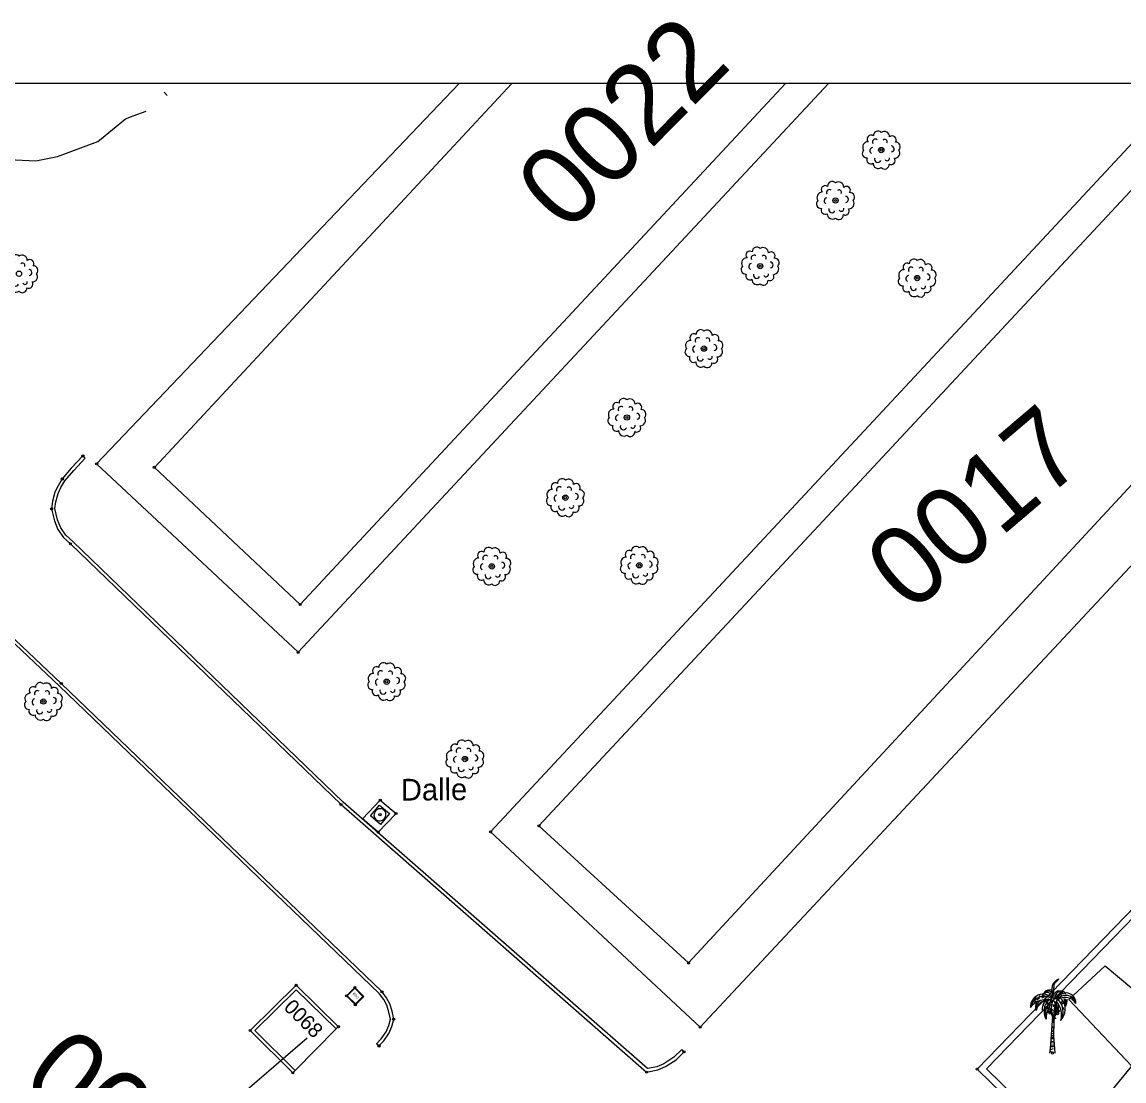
# Model space of a CAD drawing. Extents: x 344013 to 344423, y 298505 to 298795.
# Drawn here: x 344171.7 to 344222.4, y 298745.9 to 298794.7 of the extents above; entities that cross this region are included whole.
import ezdxf

# ---------------------------------------------------------------- set-up
doc = ezdxf.new("R2010")
doc.units = 0
for name, color, linetype in [('Default', 7, 'Continuous'), ('DH_CADRE -CARTOUCHE', 7, 'Continuous'), ('PC_CONCRETE', 7, 'Continuous'), ('PS_BOLT', 7, 'Continuous'), ('PS_CONST', 7, 'Continuous'), ('RES_ELECTRICITE', 7, 'Continuous'), ('TOPO_COURBE NIVEAU', 7, 'Continuous'), ('TOPO_POINT', 7, 'Continuous'), ('TOPO_TALUS-TERRAIN NATUREL', 7, 'Continuous'), ('VOIRIE_BORDURE', 7, 'Continuous'), ('VOIRIE_ESPACE VERT', 7, 'Continuous')]:
    doc.layers.add(name, color=color, linetype=linetype)

# ---------------------------------------------------------------- blocks, each defined once
blk = doc.blocks.new('REG_INC')
at = {"layer": 'Default'}
for p, q in [((0, 1), (1, 1)), ((0, 0), (0, 1)), ((1, 1), (1, 0)), ((1, 0), (0, 0))]:
    blk.add_line(p, q, dxfattribs=at)
for centre, start, end in [((0.498, 0.5), 135.00554, 180.00554), ((0.5, 0.498), 90.00577, 135.00577), ((0.5, 0.5), 45.00687, 90.00687), ((0.499, 0.499), 0.00663, 45.00663), ((0.501, 0.5), 180.00663, 225.00663), ((0.499, 0.498), 225.00686, 270.00686), ((0.499, 0.5), 270.00577, 315.00577), ((0.501, 0.499), 315.00554, 0.00554)]:
    blk.add_arc(centre, 0.44, start, end, dxfattribs=at)
blk = doc.blocks.new('RES_ELECTRICITE')
at = {"layer": 'RES_ELECTRICITE'}
for points in [[(0, 0), (0, 1), (1, 1), (1, 0)], [(0.05, 0.05), (0.05, 0.95), (0.95, 0.95), (0.95, 0.05)]]:
    blk.add_lwpolyline(points, close=True, dxfattribs=at)
blk.add_text('EEC', height=0.2, dxfattribs=at).set_placement((0.237, 0.46))
blk = doc.blocks.new('POINT_DISPLAY')
at = {"layer": 'Default'}
blk.add_circle((0, 0), 0.05, dxfattribs=at)
blk = doc.blocks.new('COCO')
at = {"layer": 'Default'}
for p, q in [((-0.037, 1.06), (0.056, 1.071)), ((0.058, 1.14), (-0.03, 1.162)), ((-0.026, 1.226), (0.061, 1.212)), ((-0.062, 0.537), (0.046, 0.552)), ((0.047, 0.655), (-0.058, 0.642)), ((-0.046, 0.891), (0.052, 0.927)), ((0.054, 0.998), (-0.041, 0.985)), ((0.046, 0.033), (-0.076, 0.051)), ((-0.073, 0.17), (0.045, 0.209)), ((0.045, 0.292), (-0.07, 0.288)), ((-0.068, 0.371), (0.045, 0.374)), ((0.045, 0.47), (-0.065, 0.453))]:
    blk.add_line(p, q, dxfattribs=at)
for points in [[(0.029, 2.551), (-0.016, 2.896), (0.002, 3.125), (0.059, 3.241), (0.173, 3.348), (0.189, 3.356), (0.282, 3.415), (0.266, 3.373), (0.2, 3.318), (0.143, 3.247), (0.093, 3.2), (0.081, 3.165), (0.057, 3.133), (0.057, 3.099), (0.06, 3.037), (0.039, 2.989), (0.039, 2.944), (0.049, 2.877), (0.037, 2.841), (0.013, 2.736)], [(-0.746, 2.559), (-0.864, 2.483)], [(-0.636, 2.639), (-0.541, 2.608)], [(-0.421, 2.58), (-0.503, 2.523)], [(-0.487, 2.68), (-0.386, 2.65)], [(-0.256, 2.553), (-0.385, 2.508)], [(0.013, 2.736), (0.036, 2.813), (0.046, 2.746)], [(0.133, 2.608), (0.185, 2.634)], [(0.196, 2.687), (0.323, 2.715)], [(0.283, 2.765), (0.331, 2.786)], [(-0.77, 2.413), (-0.836, 2.333)], [(-0.607, 2.534), (-0.704, 2.443)], [(-0.183, 2.493), (-0.348, 2.417), (-0.401, 2.307), (-0.448, 2.203), (-0.471, 2.086), (-0.474, 2.023), (-0.466, 1.973), (-0.455, 2.054), (-0.451, 2.146), (-0.387, 2.292), (-0.351, 2.354), (-0.284, 2.404), (-0.233, 2.445), (-0.012, 2.495)], [(-0.276, 2.151), (-0.329, 2.086)], [(-0.203, 2.314), (-0.274, 2.258)], [(-0.23, 2.152), (-0.237, 2.043)], [(-0.161, 2.218), (-0.158, 2.122)], [(-0.04, 2.247), (-0.081, 2.179)], [(0.015, 2.414), (-0.056, 2.352)], [(-0.025, 2.032), (0.002, 1.954)], [(0.022, 2.24), (0.043, 2.13)], [(0.081, 2.404), (0.106, 2.299)], [(0.385, 2.37), (0.469, 2.254)], [(0.473, 2.115), (0.509, 2.012)], [(-0.321, 1.997), (-0.364, 1.9)], [(-0.059, 2.024), (-0.083, 1.998)], [(-0.055, 0.716), (0.048, 0.717), (0.049, 0.787), (-0.051, 0.795)]]:
    blk.add_lwpolyline(points, dxfattribs=at)
for centre, radius in [((-0.144, 1.978), 0.0616), ((-0.187, 1.897), 0.0384), ((-0.124, 1.896), 0.0376), ((-0.11, 1.84), 0.0471), ((0.134, 1.862), 0.0549), ((0.208, 1.822), 0.0626), ((0.254, 1.938), 0.0628)]:
    blk.add_circle(centre, radius, dxfattribs=at)
for centre, radius, start, end in [((-0.427, 2.113), 0.595, 43.6121, 181.4625), ((-0.38, 1.964), 0.648, 57.9192, 166.6201), ((-0.123, 2.59), 0.323, 122.3475, 158.7636), ((-0.199, 2.618), 0.238, 4.5218, 154.101), ((-0.252, 2.556), 0.231, 4.2441, 134.2103), ((-0.16, 2.647), 0.255, 21.0861, 122.3475), ((0.376, 2.508), 0.372, 113.7681, 175.3309), ((0.376, 2.508), 0.372, 113.7681, 175.3309), ((0.418, 2.527), 0.326, 97.1248, 183.9512), ((1.025, 2.053), 0.958, 126.6858, 153.1664), ((0.59, 2.015), 0.548, 29.5654, 139.3517), ((0.618, 2.316), 0.451, 356.1627, 159.0009), ((0.609, 2.187), 0.468, 12.1077, 148.3146), ((0.344, 2.407), 0.451, 69.0817, 104.862), ((-0.157, 2.027), 0.74, 51.2475, 54.5217), ((-1.005, 1.577), 1.786, 37.5668, 40.5156), ((-0.254, 2.28), 0.869, 28.4725, 37.0965), ((0.493, 2.767), 0.0679, 35.3205, 126.6858), ((-0.054, 2.379), 0.738, 25.8194, 35.3205), ((-0.291, 1.543), 0.918, 76.7389, 142.8025), ((-0.3, 2.12), 0.482, 151.1331, 199.5942), ((-0.196, 1.874), 0.565, 78.514, 171.3504), ((-0.32, 2.055), 0.433, 119.0834, 188.7621), ((0.362, 1.922), 0.754, 136.7113, 208.8221), ((0.551, 1.79), 0.879, 137.733, 194.3716), ((0.649, 1.599), 0.949, 145.5146, 182.4528), ((0.62, 2.159), 0.753, 153.0868, 230.1124), ((0.659, 2.068), 0.718, 142.3554, 222.2794), ((-0.007, 2.465), 0.0563, 81.7475, 144.3035), ((-0.189, 1.21), 1.324, 71.3715, 81.7475), ((0.294, 2.595), 0.256, 198.6765, 199.7627), ((0.963, 1.939), 0.9, 143.9866, 203.4288), ((0.544, 1.816), 0.474, 137.1953, 172.8987), ((0.308, 2.014), 0.226, 121.4297, 182.29), ((27.302, 0.106), 27.266, 175.4791, 176.5597), ((0.311, 2.152), 0.219, 141.856, 191.5175), ((0.372, 1.847), 0.277, 133.5956, 173.487), ((0.242, 1.964), 0.147, 110.9727, 165.9756), ((0.404, 1.878), 0.354, 125.0585, 146.3893), ((0.398, 2.098), 0.301, 136.4569, 162.0685), ((0.357, 2.084), 0.244, 133.1184, 172.7534), ((-0.759, 1.958), 0.922, 344.8505, 15.8988), ((-0.404, 2.045), 0.619, 329.4666, 26.6793), ((-0.289, 2.11), 0.564, 317.8279, 12.3386), ((-0.543, 1.744), 0.96, 344.8781, 41.1461), ((-0.341, 1.9), 0.828, 46.9767, 50.1231), ((-0.341, 1.9), 0.828, 334.0687, 41.194), ((-0.157, 2.027), 0.74, 315.1472, 39.0239), ((-1.704, 1.849), 2.327, 7.5978, 16.3666), ((-0.254, 2.28), 0.869, 350.8883, 14.7063), ((-0.482, 2.552), 1.161, 339.3597, 356.5925), ((-85.428, 7.294), 85.622, 355.11326, 356.26352), ((-0.279, 1.637), 0.281, 2.1499, 36.6325), ((-0.265, 1.505), 0.316, 339.9997, 25.7228), ((0.199, 1.66), 0.176, 166.9443, 185.5966), ((0.808, 1.542), 0.777, 142.2358, 156.28)]:
    blk.add_arc(centre, radius, start, end, dxfattribs=at)
blk.add_ellipse((27.425, 0.272), major_axis=(-27.371, 0.966), ratio=0.529859, start_param=6.255729, end_param=6.369141, dxfattribs=at)
blk = doc.blocks.new('ARB1')
at = {"layer": 'Default'}
blk.add_circle((0, 0), 0.122, dxfattribs=at)
for centre, radius, start, end in [((-0.471, 0.503), 0.183, 53.9554, 222.2066), ((-0.153, 0.664), 0.211, 43.6925, 183.5969), ((0.139, 0.613), 0.241, 358.4583, 125.1928), ((0.501, 0.468), 0.183, 325.1444, 131.0175), ((-0.613, 0.139), 0.241, 88.4583, 215.1928), ((-0.373, -0.024), 0.149, 103.7092, 242.3465), ((-0.276, 0.37), 0.134, 52.4396, 209.5496), ((0.164, 0.38), 0.112, 330.5895, 133.7127), ((0.458, 0.052), 0.137, 276.6214, 88.967), ((0.613, -0.139), 0.241, 268.4583, 35.1928), ((0.664, 0.153), 0.211, 313.6925, 93.5969), ((-0.664, -0.153), 0.211, 133.6925, 273.5969), ((-0.478, -0.443), 0.19, 155.2243, 300.9377), ((-0.163, -0.42), 0.148, 159.5371, 338.1663), ((0.271, -0.38), 0.112, 210.5895, 13.7127), ((0.448, -0.483), 0.188, 243.1323, 33.0297), ((-0.139, -0.613), 0.241, 178.4583, 305.1928), ((0.153, -0.664), 0.211, 223.6925, 3.5969)]:
    blk.add_arc(centre, radius, start, end, dxfattribs=at)

msp = doc.modelspace()

# ---------------------------------------------------------------- linework, layer by layer
at = {"layer": 'DH_CADRE -CARTOUCHE'}
for points in [[(344012.906, 298504.876), (344422.906, 298504.876), (344422.906, 298791.876), (344012.906, 298791.876)], [(344194.197, 298791.876), (344177.741, 298774.193), (344184.453, 298767.878), (344206.795, 298791.876)], [(344227.296, 298791.876), (344195.443, 298757.689), (344202.327, 298751.376), (344235.016, 298786.657), (344229.42, 298791.876)], [(344186.218, 298748.441), (344186.113, 298748.334), (344184.269, 298750.136), (344182.367, 298748.262), (344184.219, 298746.424), (344184.114, 298746.317), (344182.153, 298748.263), (344184.268, 298750.346)]]:
    msp.add_lwpolyline(points, close=True, dxfattribs=at)
at = {"layer": 'PS_BOLT'}
for points in [[(344191.774, 298791.876), (344175.083, 298774.36), (344184.361, 298765.679), (344208.769, 298791.876)], [(344188.141, 298758.868), (344188.868, 298758.259), (344188.046, 298757.401), (344187.319, 298758.01)], [(344186.113, 298748.334), (344184.219, 298746.424), (344182.367, 298748.262), (344184.269, 298750.136)]]:
    msp.add_lwpolyline(points, close=True, dxfattribs=at)
msp.add_lwpolyline([(344225.308, 298791.876), (344193.218, 298757.415), (344202.864, 298748.42), (344238.059, 298786.12)], dxfattribs=at)
at = {"layer": 'PS_CONST'}
msp.add_line((344180.475, 298744.233), (344184.78, 298747.93), dxfattribs=at)
at = {"layer": 'TOPO_COURBE NIVEAU'}
msp.add_lwpolyline([(344162.165, 298787.634), (344167.122, 298788.507), (344171.346, 298788.35), (344172.281, 298788.309), (344173.289, 298788.513), (344175.141, 298789.195), (344175.212, 298789.265), (344176.409, 298790.239), (344176.771, 298790.38), (344177.37, 298790.6)], dxfattribs=at)
at = {"layer": 'TOPO_TALUS-TERRAIN NATUREL'}
msp.add_line((344178.327, 298791.316), (344178.198, 298791.476), dxfattribs=at)
at = {"layer": 'VOIRIE_BORDURE'}
for points in [[(344188.08, 298747.552), (344188.298, 298747.793), (344188.542, 298748.122), (344188.677, 298748.455), (344188.76, 298748.789), (344188.686, 298749.153), (344188.576, 298749.491), (344188.431, 298749.766), (344188.222, 298750.046), (344173.457, 298764.241), (344162.536, 298774.583), (344160.66, 298775.87), (344158.196, 298776.968), (344155.978, 298777.192), (344153.496, 298777.099)], [(344188.08, 298747.552), (344187.969, 298747.652), (344188.181, 298747.888), (344188.41, 298748.196), (344188.534, 298748.502), (344188.606, 298748.792), (344188.54, 298749.115), (344188.437, 298749.432), (344188.304, 298749.686), (344188.109, 298749.946), (344173.353, 298764.133), (344162.442, 298774.466), (344160.586, 298775.738), (344158.157, 298776.822), (344155.974, 298777.042), (344153.502, 298776.949), (344153.496, 298777.099)], [(344174.453, 298774.72), (344173.917, 298774.155), (344173.504, 298773.66), (344173.311, 298773.344), (344173.168, 298773.046), (344173.054, 298772.636), (344173.012, 298772.284), (344173.147, 298771.735), (344173.306, 298771.334), (344173.559, 298770.965), (344173.884, 298770.674), (344186.334, 298758.674), (344200.397, 298746.348), (344200.913, 298746.454), (344201.268, 298746.604), (344201.755, 298746.92), (344202.124, 298747.284)], [(344202.124, 298747.284), (344202.019, 298747.391), (344201.66, 298747.038), (344201.198, 298746.737), (344200.868, 298746.598), (344200.44, 298746.51), (344186.435, 298758.785), (344173.986, 298770.784), (344173.672, 298771.065), (344173.439, 298771.405), (344173.291, 298771.781), (344173.165, 298772.294), (344173.201, 298772.607), (344173.309, 298772.994), (344173.443, 298773.272), (344173.626, 298773.573), (344174.029, 298774.055), (344174.562, 298774.616), (344174.453, 298774.72)]]:
    msp.add_lwpolyline(points, dxfattribs=at)
at = {"layer": 'VOIRIE_ESPACE VERT'}
for points in [[(344228.609, 298733.786), (344215.617, 298746.488), (344237.992, 298769.574), (344251.389, 298756.925), (344242.713, 298747.917), (344242.041, 298748.012), (344241.328, 298747.986), (344240.625, 298747.821), (344240.024, 298747.565), (344239.421, 298747.187), (344239.008, 298746.783), (344238.537, 298746.143), (344238.196, 298745.471), (344238.047, 298744.807), (344237.999, 298744.129), (344238.073, 298743.423)], [(344228.605, 298734.21), (344216.04, 298746.493), (344238.001, 298769.152), (344250.963, 298756.915), (344242.603, 298748.236), (344242.057, 298748.313), (344241.288, 298748.284), (344240.531, 298748.107), (344239.884, 298747.832), (344239.235, 298747.424), (344238.781, 298746.98), (344238.281, 298746.301), (344237.912, 298745.574), (344237.75, 298744.85), (344237.698, 298744.124), (344237.76, 298743.532)]]:
    msp.add_lwpolyline(points, close=True, dxfattribs=at)
msp.add_lwpolyline([(344222.418, 298742.507), (344220.739, 298744.193), (344222.741, 298746.629), (344219.835, 298749.685), (344221.506, 298751.241), (344224.052, 298749.112)], dxfattribs=at)

# ---------------------------------------------------------------- block references
at = {"layer": 'PC_CONCRETE', "xscale": 0.6491416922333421, "yscale": 0.6060069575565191, "rotation": -130.57380000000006}
msp.add_blockref('REG_INC', (344188.107, 298758.644), dxfattribs=at)
at = {"layer": 'RES_ELECTRICITE', "xscale": 0.58423256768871, "yscale": 0.544041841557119, "rotation": -45.074298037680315}
msp.add_blockref('RES_ELECTRICITE', (344186.584, 298749.863), dxfattribs=at)
at = {"layer": 'TOPO_POINT'}
for p in [(344211.201, 298788.805), (344209.095, 298786.481), (344205.628, 298783.461), (344212.856, 298782.91), (344203.04, 298779.662), (344199.493, 298776.492), (344174.453, 298774.72), (344175.083, 298774.36), (344177.741, 298774.193), (344173.504, 298773.66), (344196.662, 298772.798), (344173.012, 298772.284), (344173.884, 298770.674), (344193.275, 298769.636), (344200.064, 298769.683), (344184.453, 298767.878), (344184.361, 298765.679), (344173.457, 298764.241), (344188.436, 298764.326), (344172.634, 298763.411), (344192.037, 298760.764), (344186.334, 298758.674), (344188.141, 298758.868), (344188.126, 298758.202), (344188.868, 298758.259), (344188.046, 298757.401), (344193.218, 298757.415), (344195.443, 298757.689), (344202.327, 298751.376), (344184.268, 298750.346), (344186.584, 298749.863), (344186.972, 298750.244), (344188.222, 298750.046), (344186.996, 298749.449), (344188.76, 298748.789), (344182.153, 298748.263), (344186.218, 298748.441), (344202.864, 298748.42), (344188.08, 298747.552), (344202.124, 298747.284), (344219.085, 298747.226), (344184.114, 298746.317), (344200.397, 298746.348), (344215.617, 298746.488)]:
    msp.add_blockref('POINT_DISPLAY', p, dxfattribs=at)
at = {"layer": 'VOIRIE_ESPACE VERT'}
for name, p in [('ARB1', (344211.201, 298788.805)), ('ARB1', (344209.095, 298786.481)), ('ARB1', (344205.628, 298783.461)), ('ARB1', (344171.512, 298783.112)), ('ARB1', (344212.856, 298782.91)), ('ARB1', (344203.04, 298779.662)), ('ARB1', (344199.493, 298776.492)), ('ARB1', (344196.662, 298772.798)), ('ARB1', (344193.275, 298769.636)), ('ARB1', (344200.064, 298769.683)), ('ARB1', (344188.436, 298764.326)), ('ARB1', (344172.634, 298763.411)), ('ARB1', (344192.037, 298760.764)), ('COCO', (344219.085, 298747.226))]:
    msp.add_blockref(name, p, dxfattribs=at)

# ---------------------------------------------------------------- texts
at = {"layer": 'PS_CONST'}
for s, height, rotation, p in [('0022', 3.662, 45.3665, (344196.737, 298784.916)), ('0017', 3.662, 40.3665, (344212.533, 298767.422)), ('Dalle', 1.0003, 0.3665, (344189.095, 298758.851)), ('0068', 0.6786, 315.2605, (344183.657, 298749.287)), ('0068', 3.662, 320.3665, (344171.524, 298745.815))]:
    msp.add_text(s, height=height, rotation=rotation, dxfattribs=at).set_placement(p)

doc.saveas('drawing.dxf')
